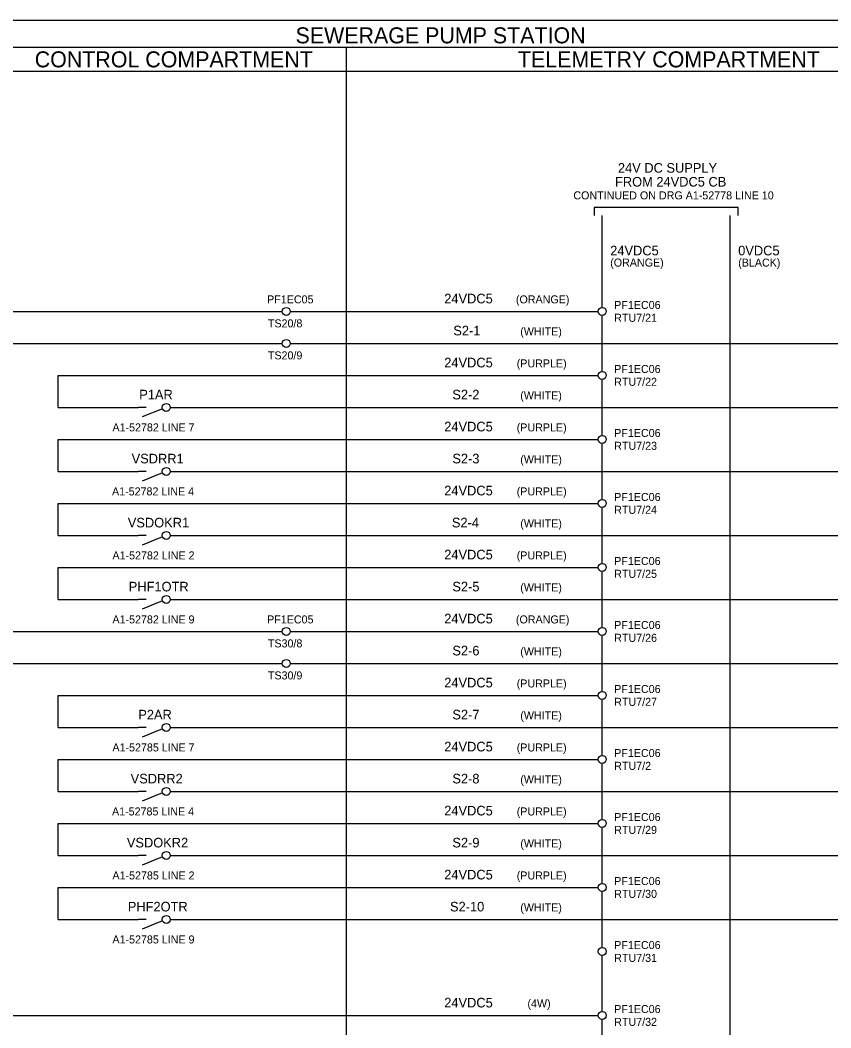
# Model space of a CAD drawing. Extents: x 0 to 841, y 0 to 594.
# Drawn here: x 428.1 to 681.5, y 266.1 to 581 of the extents above; entities that cross this region are included whole.
import ezdxf

# ---------------------------------------------------------------- set-up
doc = ezdxf.new("R2010")
doc.units = 0
for name, color, linetype in [('A1BORDER', 7, 'Continuous'), ('Default', 7, 'Continuous'), ('Level 1', 7, 'Continuous'), ('Level 10', 7, 'Continuous'), ('Level 2', 7, 'Continuous'), ('Level 5', 7, 'Continuous')]:
    doc.layers.add(name, color=color, linetype=linetype)

msp = doc.modelspace()

# ---------------------------------------------------------------- linework, layer by layer
at = {"layer": 'A1BORDER'}
msp.add_line((28, 581), (829, 581), dxfattribs=at)
at = {"layer": 'Default'}
msp.add_line((650, 140), (650, 520), dxfattribs=at)
at = {"layer": 'Level 1'}
for p, q in [((829, 572.5), (160, 572.5)), ((530, 572.5), (530, 57)), ((829, 565), (160, 565)), ((610, 491.25), (610, 520)), ((320, 490), (510, 490)), ((510, 490), (510, 490)), ((512.5, 490), (512.5, 490)), ((512.5, 490), (608.75, 490)), ((610, 471.25), (610, 488.75)), ((360, 480), (510, 480)), ((510, 480), (510, 480)), ((512.5, 480), (512.5, 480)), ((512.5, 480), (690, 480)), ((440, 460), (440, 470)), ((440, 470), (608.75, 470)), ((610, 451.25), (610, 468.75)), ((440, 460), (465, 460)), ((467.5, 460), (465, 460)), ((465, 460), (465, 460)), ((475, 460), (690, 460)), ((475, 460), (475, 460)), ((440, 440), (440, 450)), ((440, 450), (608.75, 450)), ((610, 431.25), (610, 448.75)), ((440, 440), (465, 440)), ((467.5, 440), (465, 440)), ((465, 440), (465, 440)), ((475, 440), (690, 440)), ((475, 440), (475, 440)), ((440, 420), (440, 430)), ((440, 430), (608.75, 430)), ((610, 411.25), (610, 428.75)), ((440, 420), (465, 420)), ((467.5, 420), (465, 420)), ((465, 420), (465, 420)), ((475, 420), (690, 420)), ((475, 420), (475, 420)), ((440, 400), (440, 410)), ((440, 410), (608.75, 410)), ((610, 391.25), (610, 408.75)), ((440, 400), (465, 400)), ((467.5, 400), (465, 400)), ((465, 400), (465, 400)), ((475, 400), (690, 400)), ((475, 400), (475, 400)), ((320, 390), (510, 390)), ((510, 390), (510, 390)), ((512.5, 390), (512.5, 390)), ((512.5, 390), (608.75, 390)), ((610, 371.25), (610, 388.75)), ((360, 380), (510, 380)), ((510, 380), (510, 380)), ((512.5, 380), (512.5, 380)), ((512.5, 380), (690, 380)), ((440, 360), (440, 370)), ((440, 370), (608.75, 370)), ((610, 351.25), (610, 368.75)), ((440, 360), (465, 360)), ((467.5, 360), (465, 360)), ((465, 360), (465, 360)), ((475, 360), (690, 360)), ((475, 360), (475, 360)), ((440, 340), (440, 350)), ((440, 350), (608.75, 350)), ((610, 331.25), (610, 348.75)), ((440, 340), (465, 340)), ((467.5, 340), (465, 340)), ((465, 340), (465, 340)), ((475, 340), (690, 340)), ((475, 340), (475, 340)), ((440, 320), (440, 330)), ((440, 330), (608.75, 330)), ((610, 311.25), (610, 328.75)), ((440, 320), (465, 320)), ((467.5, 320), (465, 320)), ((465, 320), (465, 320)), ((475, 320), (690, 320)), ((475, 320), (475, 320)), ((440, 300), (440, 310)), ((440, 310), (608.75, 310)), ((610, 291.25), (610, 308.75)), ((440, 300), (465, 300)), ((467.5, 300), (465, 300)), ((465, 300), (465, 300)), ((475, 300), (690, 300)), ((475, 300), (475, 300)), ((610, 271.25), (610, 288.75)), ((272.5, 270), (608.75, 270)), ((610, 251.25), (610, 268.75))]:
    msp.add_line(p, q, dxfattribs=at)
msp.add_lwpolyline([(652.5, 520), (652.5, 522.5), (607.5, 522.5), (607.5, 520)], dxfattribs=at)
at = {"layer": 'Level 10'}
for p, q in [((472.59, 459.54), (466.25, 457)), ((472.59, 439.54), (466.25, 437)), ((472.59, 419.54), (466.25, 417)), ((472.59, 399.54), (466.25, 397)), ((472.59, 359.54), (466.25, 357)), ((472.59, 339.54), (466.25, 337)), ((472.59, 319.54), (466.25, 317)), ((472.59, 299.54), (466.25, 297))]:
    msp.add_line(p, q, dxfattribs=at)
for centre in [(511.25, 490), (610, 490), (511.25, 480), (610, 470), (473.75, 460), (610, 450), (473.75, 440), (610, 430), (473.75, 420), (610, 410), (473.75, 400), (511.25, 390), (610, 390), (511.25, 380), (610, 370), (473.75, 360), (610, 350), (473.75, 340), (610, 330), (473.75, 320), (610, 310), (473.75, 300), (610, 290), (610, 270)]:
    msp.add_circle(centre, 1.25, dxfattribs=at)

# ---------------------------------------------------------------- texts
at = {"layer": 'Level 1'}
for s, height, p in [('SEWERAGE PUMP STATION', 5, (514.16, 573.75)), ('CONTROL COMPARTMENT', 5, (432.65, 566.25)), ('TELEMETRY COMPARTMENT', 5, (583.66, 566.25)), ('24V DC SUPPLY', 3, (614.91, 533.34)), ('FROM 24VDC5 CB', 3, (614.01, 529)), ('CONTINUED ON DRG A1-52778 LINE 10', 2.5, (600.99, 525)), ('24VDC5', 3, (612.5, 507.5)), ('0VDC5', 3, (652.5, 507.5)), ('(ORANGE)', 2.5, (612.5, 504)), ('(BLACK)', 2.5, (652.5, 504)), ('PF1EC05', 2.5, (505.28, 492.5)), ('24VDC5', 3, (560.63, 492.5)), ('(ORANGE)', 2.5, (583.03, 492.5)), ('PF1EC06', 2.5, (613.75, 490.75)), ('RTU7/21', 2.5, (613.75, 486.75)), ('TS20/8', 2.5, (505.52, 485)), ('S2-1', 3, (563.46, 482.5)), ('(WHITE)', 2.5, (584.39, 482.5)), ('TS20/9', 2.5, (505.52, 475)), ('24VDC5', 3, (560.63, 472.5)), ('(PURPLE)', 2.5, (583.28, 472.5)), ('PF1EC06', 2.5, (613.75, 470.75)), ('RTU7/22', 2.5, (613.75, 466.75)), ('S2-2', 3, (563.16, 462.5)), ('(WHITE)', 2.5, (584.39, 462.5)), ('24VDC5', 3, (560.63, 452.5)), ('(PURPLE)', 2.5, (583.28, 452.5)), ('PF1EC06', 2.5, (613.75, 450.75)), ('RTU7/23', 2.5, (613.75, 446.75)), ('S2-3', 3, (563.17, 442.5)), ('(WHITE)', 2.5, (584.4, 442.5)), ('24VDC5', 3, (560.63, 432.5)), ('(PURPLE)', 2.5, (583.28, 432.5)), ('PF1EC06', 2.5, (613.75, 430.75)), ('RTU7/24', 2.5, (613.75, 426.75)), ('S2-4', 3, (563.02, 422.5)), ('(WHITE)', 2.5, (584.4, 422.5)), ('24VDC5', 3, (560.63, 412.5)), ('(PURPLE)', 2.5, (583.28, 412.5)), ('PF1EC06', 2.5, (613.75, 410.75)), ('RTU7/25', 2.5, (613.75, 406.75)), ('S2-5', 3, (563.17, 402.5)), ('(WHITE)', 2.5, (584.4, 402.5)), ('PF1EC05', 2.5, (505.28, 392.5)), ('24VDC5', 3, (560.63, 392.5)), ('(ORANGE)', 2.5, (583.03, 392.5)), ('PF1EC06', 2.5, (613.75, 390.75)), ('TS30/8', 2.5, (505.52, 385)), ('RTU7/26', 2.5, (613.75, 386.75)), ('S2-6', 3, (563.17, 382.5)), ('(WHITE)', 2.5, (584.4, 382.5)), ('TS30/9', 2.5, (505.52, 375)), ('24VDC5', 3, (560.63, 372.5)), ('(PURPLE)', 2.5, (583.28, 372.5)), ('S2-7', 3, (563.17, 362.5)), ('(WHITE)', 2.5, (584.4, 362.5)), ('24VDC5', 3, (560.63, 352.5)), ('(PURPLE)', 2.5, (583.28, 352.5)), ('S2-8', 3, (563.17, 342.5)), ('(WHITE)', 2.5, (584.4, 342.5)), ('24VDC5', 3, (560.63, 332.5)), ('(PURPLE)', 2.5, (583.28, 332.5)), ('S2-9', 3, (563.17, 322.5)), ('(WHITE)', 2.5, (584.4, 322.5)), ('24VDC5', 3, (560.63, 312.5)), ('(PURPLE)', 2.5, (583.28, 312.5)), ('S2-10', 3, (562.43, 302.5)), ('(WHITE)', 2.5, (584.4, 302.5)), ('24VDC5', 3, (560.63, 272.5)), ('(4W)', 2.5, (586.64, 272.5))]:
    msp.add_text(s, height=height, dxfattribs=at).set_placement(p)
at = {"layer": 'Level 2'}
for s, p in [('PF1EC06', (613.75, 370.75)), ('RTU7/27', (613.75, 366.75)), ('PF1EC06', (613.75, 350.75)), ('RTU7/2', (613.75, 346.75)), ('PF1EC06', (613.75, 330.75)), ('RTU7/29', (613.75, 326.75)), ('PF1EC06', (613.75, 310.75)), ('RTU7/30', (613.75, 306.75)), ('PF1EC06', (613.75, 290.75)), ('RTU7/31', (613.75, 286.75)), ('PF1EC06', (613.75, 270.75)), ('RTU7/32', (613.75, 266.75))]:
    msp.add_text(s, height=2.5, dxfattribs=at).set_placement(p)
at = {"layer": 'Level 5'}
for s, height, p in [('P1AR', 3, (465.31, 462.5)), ('A1-52782 LINE 7', 2.5, (456.93, 452.5)), ('VSDRR1', 3, (462.92, 442.5)), ('A1-52782 LINE 4', 2.5, (456.8, 432.5)), ('VSDOKR1', 3, (461.73, 422.5)), ('A1-52782 LINE 2', 2.5, (456.93, 412.5)), ('PHF1OTR', 3, (462.03, 402.5)), ('A1-52782 LINE 9', 2.5, (456.93, 392.5)), ('P2AR', 3, (465.01, 362.5)), ('A1-52785 LINE 7', 2.5, (456.93, 352.5)), ('VSDRR2', 3, (462.62, 342.5)), ('A1-52785 LINE 4', 2.5, (456.8, 332.5)), ('VSDOKR2', 3, (461.43, 322.5)), ('A1-52785 LINE 2', 2.5, (456.93, 312.5)), ('PHF2OTR', 3, (461.73, 302.5)), ('A1-52785 LINE 9', 2.5, (456.93, 292.5))]:
    msp.add_text(s, height=height, dxfattribs=at).set_placement(p)

doc.saveas('drawing.dxf')
